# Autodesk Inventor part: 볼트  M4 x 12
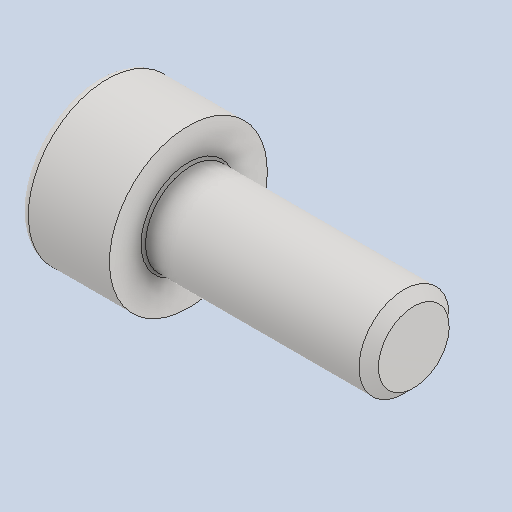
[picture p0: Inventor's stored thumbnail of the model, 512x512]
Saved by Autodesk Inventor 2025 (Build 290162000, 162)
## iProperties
Created: 2025-08
Part Number: 볼트  M4 x 12
Material: 스테인리스강
Description: 6각머리 태핑 나사
Document SubType Name: Modeling
Designer: infra04
Density: 8.08 g/cm^3
Appearance: 기본값
Author: jhkim
Sending System: Autodesk Inventor 2026
Preprocessor: ST-DEVELOPER v20.1
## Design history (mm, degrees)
feature "Solid1"
node "솔리드1"
